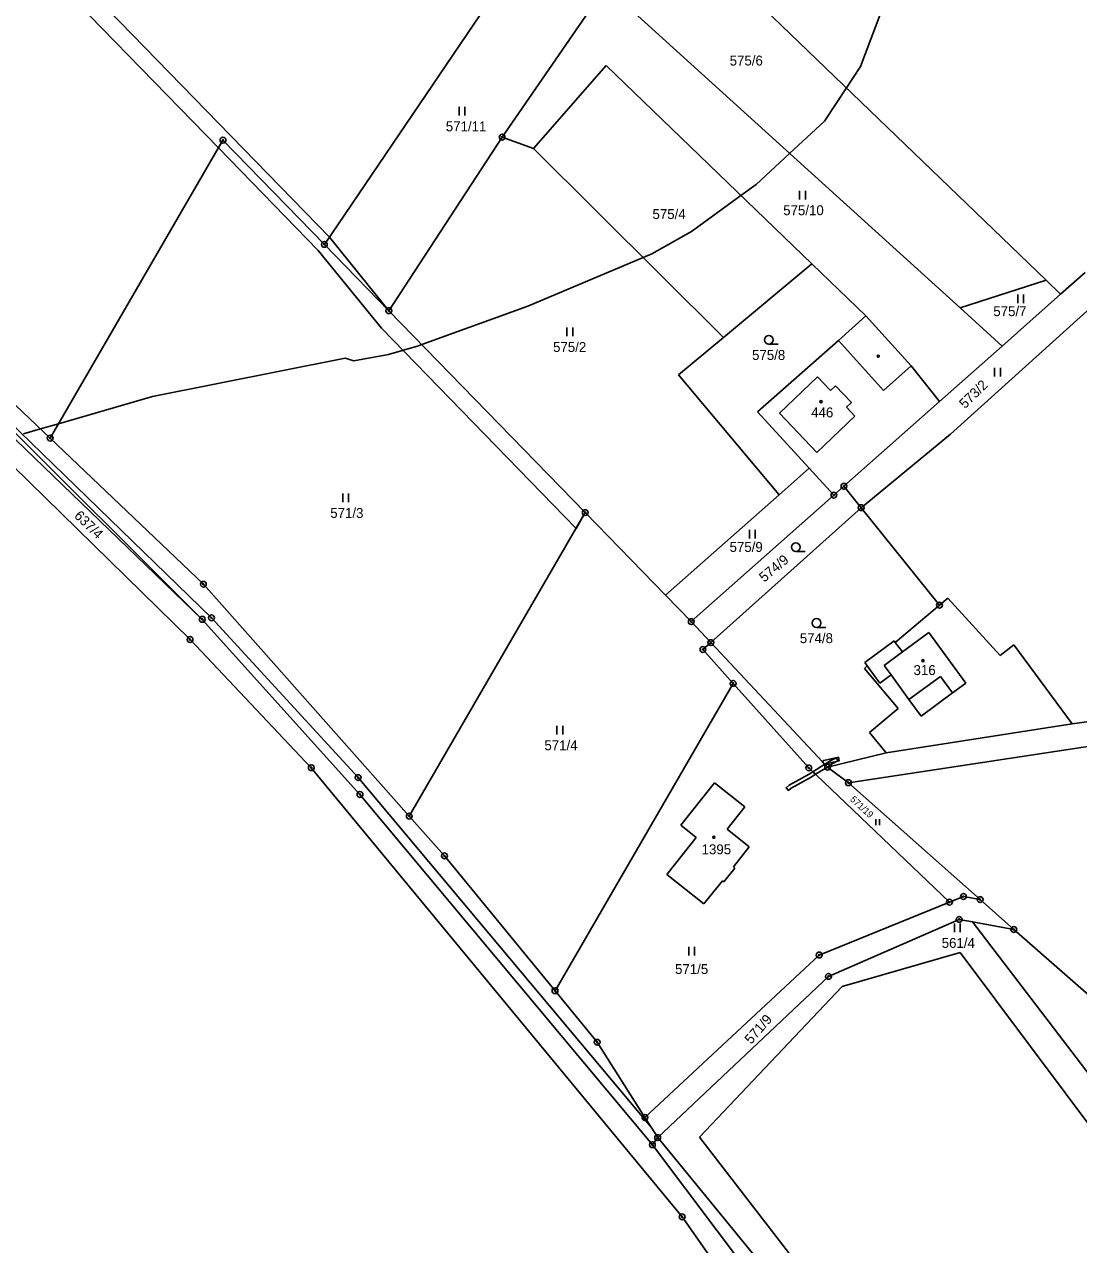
# Model space of a CAD drawing. Extents: x -439246 to -433691, y -1130252 to -1121148.
# Drawn here: x -437188.8 to -437008, y -1124679.8 to -1124470.4 of the extents above; entities that cross this region are included whole.
import ezdxf

# ---------------------------------------------------------------- set-up
doc = ezdxf.new("R2010")
doc.units = 0
for name, color, linetype in [('Vrstva 1', 7, 'Continuous'), ('Vrstva 18', 7, 'Continuous'), ('Vrstva 19', 7, 'Continuous'), ('Vrstva 24', 7, 'Continuous'), ('Vrstva 25', 7, 'Continuous'), ('Vrstva 3', 7, 'Continuous'), ('Vrstva 30', 7, 'Continuous'), ('Vrstva 37', 7, 'Continuous'), ('Vrstva 4', 7, 'Continuous'), ('Vrstva 52', 7, 'Continuous')]:
    doc.layers.add(name, color=color, linetype=linetype)

msp = doc.modelspace()

# ---------------------------------------------------------------- linework, layer by layer
at = {"layer": 'Vrstva 1'}
for p, q in [((-437160.38, -1124575.95), (-437208.36, -1124528.97)), ((-437194.11, -1124535.93), (-437156.69, -1124572.25)), ((-437156.69, -1124572.25), (-437131.53, -1124599.65)), ((-437139.58, -1124597.95), (-437160.38, -1124575.95)), ((-437044.66, -1124579.93), (-437039.61, -1124576.21)), ((-437039.61, -1124576.21), (-437039.43, -1124576.46)), ((-437044.72, -1124580.91), (-437044.24, -1124580.5)), ((-437044.24, -1124580.5), (-437044.66, -1124579.93)), ((-437075.97, -1124675.01), (-437139.58, -1124597.95)), ((-437131.53, -1124599.65), (-437081.31, -1124659.62)), ((-437076.2, -1124607.79), (-437070.42, -1124600.53)), ((-437070.42, -1124600.53), (-437065.2, -1124604.66)), ((-437065.2, -1124604.66), (-437068.26, -1124608.5)), ((-437073.55, -1124609.9), (-437076.2, -1124607.79)), ((-437068.26, -1124608.5), (-437064.45, -1124611.53)), ((-437078.59, -1124616.26), (-437073.55, -1124609.9)), ((-437064.45, -1124611.53), (-437067.17, -1124614.98)), ((-437066.93, -1124615.17), (-437068.84, -1124617.56)), ((-437067.17, -1124614.98), (-437066.93, -1124615.17)), ((-437072.23, -1124621.33), (-437078.59, -1124616.26)), ((-437069.08, -1124617.38), (-437072.23, -1124621.33)), ((-437068.84, -1124617.56), (-437069.08, -1124617.38)), ((-437082.35, -1124657.98), (-437081.31, -1124659.62)), ((-437081.31, -1124659.62), (-437080.17, -1124661.42)), ((-437062.23, -1124694.64), (-437075.97, -1124675.01))]:
    msp.add_line(p, q, dxfattribs=at)
for points in [[(-437099.75, -1124431.26), (-437013.54, -1124514.31)], [(-437098.98, -1124451.49), (-437137.34, -1124508.17)], [(-437106.86, -1124489.77), (-437089.09, -1124463.94)], [(-437028.31, -1124519.08), (-437089.09, -1124463.94)], [(-437101.46, -1124491.7), (-437089.02, -1124477.46)], [(-437089.02, -1124477.46), (-437053.74, -1124511.51)], [(-437154.73, -1124490.28), (-437184.38, -1124541.41)], [(-437137.34, -1124508.17), (-437154.73, -1124490.28)], [(-437126.28, -1124519.54), (-437106.86, -1124489.77)], [(-437106.86, -1124489.77), (-437101.46, -1124491.7)], [(-437068.88, -1124524.14), (-437101.46, -1124491.7)], [(-437229.3, -1124501.69), (-437158.28, -1124572.5)], [(-437230.24, -1124503.19), (-437158.28, -1124572.5)], [(-437137.34, -1124508.17), (-437126.28, -1124519.54)], [(-437184.38, -1124541.41), (-437218.63, -1124508.88)], [(-437053.74, -1124511.51), (-437068.88, -1124524.14)], [(-437053.74, -1124511.51), (-437044.48, -1124520.41)], [(-437028.31, -1124519.08), (-437013.54, -1124514.31)], [(-437013.54, -1124514.31), (-437011.05, -1124516.71)], [(-437011.05, -1124516.71), (-437006.87, -1124513)], [(-437029.94, -1124540.74), (-437002.46, -1124515.91)], [(-437021.1, -1124525.62), (-437011.05, -1124516.71)], [(-437126.28, -1124519.54), (-437092.59, -1124554.19)], [(-437044.48, -1124520.41), (-437049.17, -1124524.64)], [(-437044.48, -1124520.41), (-437036.71, -1124529)], [(-437021.1, -1124525.62), (-437028.31, -1124519.08)], [(-437068.88, -1124524.14), (-437076.58, -1124530.56)], [(-437049.17, -1124524.64), (-437063.05, -1124536.87)], [(-437031.84, -1124535.14), (-437021.1, -1124525.62)], [(-437036.71, -1124529), (-437031.84, -1124535.14)], [(-437076.58, -1124530.56), (-437059.35, -1124551.15)], [(-437048.22, -1124549.67), (-437031.84, -1124535.14)], [(-437063.05, -1124536.87), (-437054.16, -1124546.58)], [(-437184.38, -1124541.41), (-437158.09, -1124566.48)], [(-437045.28, -1124553.34), (-437029.94, -1124540.74)], [(-437059.35, -1124551.15), (-437054.16, -1124546.58)], [(-437054.16, -1124546.58), (-437049.94, -1124551.19)], [(-437049.94, -1124551.19), (-437048.22, -1124549.67)], [(-437045.28, -1124553.34), (-437048.22, -1124549.67)], [(-437078.84, -1124568.33), (-437059.35, -1124551.15)], [(-437074.41, -1124572.89), (-437049.94, -1124551.19)], [(-437092.59, -1124554.19), (-437122.78, -1124606.26)], [(-437078.84, -1124568.33), (-437092.59, -1124554.19)], [(-437071.04, -1124576.49), (-437045.28, -1124553.34)], [(-437031.83, -1124570.07), (-437045.28, -1124553.34)], [(-437158.09, -1124566.48), (-437122.78, -1124606.26)], [(-437074.41, -1124572.89), (-437078.84, -1124568.33)], [(-437031.83, -1124570.07), (-437030.41, -1124568.88)], [(-437030.41, -1124568.88), (-437021.45, -1124578.7)], [(-437031.83, -1124570.07), (-437039.43, -1124576.46)], [(-437158.28, -1124572.5), (-437131.23, -1124602.56)], [(-437071.04, -1124576.49), (-437074.41, -1124572.89)], [(-437072.41, -1124577.67), (-437071.04, -1124576.49)], [(-437051.02, -1124597.87), (-437071.04, -1124576.49)], [(-437019.1, -1124576.85), (-437021.45, -1124578.7)], [(-437019.1, -1124576.85), (-437009.08, -1124590.45)], [(-437067.21, -1124583.49), (-437072.41, -1124577.67)], [(-437044.72, -1124580.91), (-437038.94, -1124587.78)], [(-437097.78, -1124636.21), (-437067.21, -1124583.49)], [(-437054.26, -1124597.99), (-437067.21, -1124583.49)], [(-437009.08, -1124590.45), (-436975.07, -1124585.71)], [(-437038.94, -1124587.78), (-437043.86, -1124591.93)], [(-437047.46, -1124600.52), (-436975.87, -1124589.68)], [(-437043.86, -1124591.93), (-437040.96, -1124595.38)], [(-437040.96, -1124595.38), (-437009.08, -1124590.45)], [(-437051.02, -1124597.87), (-437040.96, -1124595.38)], [(-437030.11, -1124621.02), (-437054.26, -1124597.99)], [(-437047.46, -1124600.52), (-437051.02, -1124597.87)], [(-437024.86, -1124620.58), (-437047.46, -1124600.52)], [(-437131.23, -1124602.56), (-437081.08, -1124662.64)], [(-437122.78, -1124606.26), (-437116.73, -1124613.07)], [(-437116.73, -1124613.07), (-437097.78, -1124636.21)], [(-437052.48, -1124630.09), (-437030.11, -1124621.02)], [(-437030.11, -1124621.02), (-437027.73, -1124620.05)], [(-437027.73, -1124620.05), (-437024.86, -1124620.58)], [(-437024.86, -1124620.58), (-437019.08, -1124625.71)], [(-437028.46, -1124623.98), (-437050.88, -1124633.76)], [(-437026.18, -1124624.4), (-437028.46, -1124623.98)], [(-436988.93, -1124673.14), (-437026.18, -1124624.4)], [(-437019.08, -1124625.71), (-437026.18, -1124624.4)], [(-437019.08, -1124625.71), (-436938.54, -1124696.3)], [(-437048.54, -1124635.49), (-437028.26, -1124629.67)], [(-437028.26, -1124629.67), (-436992.11, -1124678.02)], [(-437082.35, -1124657.98), (-437052.48, -1124630.09)], [(-437080.17, -1124661.42), (-437050.88, -1124633.76)], [(-437073, -1124661.34), (-437048.54, -1124635.49)], [(-437097.78, -1124636.21), (-437090.54, -1124645.06)], [(-437090.54, -1124645.06), (-437082.35, -1124657.98)], [(-437080.17, -1124661.42), (-437081.08, -1124662.64)], [(-437081.08, -1124662.64), (-437058.87, -1124692.18)], [(-437080.17, -1124661.42), (-437053.17, -1124694.4)], [(-437011.99, -1124740.43), (-437073, -1124661.34)]]:
    msp.add_lwpolyline(points, dxfattribs=at)
at = {"layer": 'Vrstva 24'}
for centre, radius in [((-437106.86, -1124489.77), 0.5), ((-437154.73, -1124490.28), 0.5), ((-437154.73, -1124490.28), 0.1), ((-437106.86, -1124489.77), 0.1), ((-437137.34, -1124508.17), 0.5), ((-437137.34, -1124508.17), 0.1), ((-437126.28, -1124519.54), 0.5), ((-437126.28, -1124519.54), 0.1), ((-437184.38, -1124541.41), 0.5), ((-437184.38, -1124541.41), 0.1), ((-437048.22, -1124549.67), 0.5), ((-437048.22, -1124549.67), 0.1), ((-437049.94, -1124551.19), 0.5), ((-437049.94, -1124551.19), 0.1), ((-437092.59, -1124554.19), 0.5), ((-437092.59, -1124554.19), 0.1), ((-437045.28, -1124553.34), 0.5), ((-437045.28, -1124553.34), 0.1), ((-437158.09, -1124566.48), 0.5), ((-437158.09, -1124566.48), 0.1), ((-437031.83, -1124570.07), 0.5), ((-437031.83, -1124570.07), 0.1), ((-437158.28, -1124572.5), 0.5), ((-437158.28, -1124572.5), 0.1), ((-437156.69, -1124572.25), 0.5), ((-437156.69, -1124572.25), 0.1), ((-437074.41, -1124572.89), 0.5), ((-437074.41, -1124572.89), 0.1), ((-437160.38, -1124575.95), 0.5), ((-437160.38, -1124575.95), 0.1), ((-437072.41, -1124577.67), 0.5), ((-437071.04, -1124576.49), 0.5), ((-437071.04, -1124576.49), 0.1), ((-437072.41, -1124577.67), 0.1), ((-437067.21, -1124583.49), 0.5), ((-437067.21, -1124583.49), 0.1), ((-437139.58, -1124597.95), 0.5), ((-437139.58, -1124597.95), 0.1), ((-437054.26, -1124597.99), 0.5), ((-437054.26, -1124597.99), 0.1), ((-437051.02, -1124597.87), 0.5), ((-437051.02, -1124597.87), 0.1), ((-437131.53, -1124599.65), 0.5), ((-437131.53, -1124599.65), 0.1), ((-437047.46, -1124600.52), 0.5), ((-437047.46, -1124600.52), 0.1), ((-437131.23, -1124602.56), 0.5), ((-437131.23, -1124602.56), 0.1), ((-437122.78, -1124606.26), 0.5), ((-437122.78, -1124606.26), 0.1), ((-437116.73, -1124613.07), 0.5), ((-437116.73, -1124613.07), 0.1), ((-437030.11, -1124621.02), 0.5), ((-437030.11, -1124621.02), 0.1), ((-437027.73, -1124620.05), 0.5), ((-437027.73, -1124620.05), 0.1), ((-437024.86, -1124620.58), 0.5), ((-437024.86, -1124620.58), 0.1), ((-437028.46, -1124623.98), 0.5), ((-437028.46, -1124623.98), 0.1), ((-437019.08, -1124625.71), 0.5), ((-437019.08, -1124625.71), 0.1), ((-437052.48, -1124630.09), 0.5), ((-437052.48, -1124630.09), 0.1), ((-437050.88, -1124633.76), 0.5), ((-437050.88, -1124633.76), 0.1), ((-437097.78, -1124636.21), 0.5), ((-437097.78, -1124636.21), 0.1), ((-437090.54, -1124645.06), 0.5), ((-437090.54, -1124645.06), 0.1), ((-437082.35, -1124657.98), 0.5), ((-437082.35, -1124657.98), 0.1), ((-437080.17, -1124661.42), 0.5), ((-437081.08, -1124662.64), 0.5), ((-437081.08, -1124662.64), 0.1), ((-437080.17, -1124661.42), 0.1), ((-437075.97, -1124675.01), 0.5), ((-437075.97, -1124675.01), 0.1)]:
    msp.add_circle(centre, radius, dxfattribs=at)
at = {"layer": 'Vrstva 25'}
for p, q in [((-437114.24, -1124486.07), (-437114.24, -1124484.57)), ((-437113.24, -1124486.07), (-437113.24, -1124484.57)), ((-437055.84, -1124500.46), (-437055.84, -1124498.96)), ((-437054.84, -1124500.46), (-437054.84, -1124498.96)), ((-437018.41, -1124518.27), (-437018.41, -1124516.77)), ((-437017.41, -1124518.27), (-437017.41, -1124516.77)), ((-437095.74, -1124523.93), (-437095.74, -1124522.43)), ((-437094.74, -1124523.93), (-437094.74, -1124522.43)), ((-437061.11, -1124525.29), (-437059.51, -1124525.29)), ((-437022.39, -1124530.84), (-437022.39, -1124529.34)), ((-437021.39, -1124530.84), (-437021.39, -1124529.34)), ((-437134.19, -1124552.4), (-437134.19, -1124550.9)), ((-437133.19, -1124552.4), (-437133.19, -1124550.9)), ((-437064.43, -1124558.65), (-437064.43, -1124557.15)), ((-437063.43, -1124558.65), (-437063.43, -1124557.15)), ((-437056.48, -1124560.86), (-437054.88, -1124560.86)), ((-437052.91, -1124573.88), (-437051.31, -1124573.88)), ((-437097.45, -1124592.26), (-437097.45, -1124590.76)), ((-437096.45, -1124592.26), (-437096.45, -1124590.76)), ((-437042.78, -1124607.82), (-437042.78, -1124606.81)), ((-437042.1, -1124607.82), (-437042.1, -1124606.81)), ((-437029.27, -1124626.17), (-437029.27, -1124624.67)), ((-437028.27, -1124626.17), (-437028.27, -1124624.67)), ((-437074.85, -1124630.2), (-437074.85, -1124628.7)), ((-437073.85, -1124630.2), (-437073.85, -1124628.7))]:
    msp.add_line(p, q, dxfattribs=at)
for centre, radius in [((-437061.11, -1124524.54), 0.75), ((-437042.33, -1124527.34), 0.175), ((-437052.16, -1124535.15), 0.175), ((-437056.48, -1124560.11), 0.75), ((-437052.91, -1124573.13), 0.75), ((-437034.67, -1124579.59), 0.175), ((-437070.53, -1124609.89), 0.175)]:
    msp.add_circle(centre, radius, dxfattribs=at)
at = {"layer": 'Vrstva 3'}
for points in [[(-437059.27, -1124537.13), (-437052.76, -1124530.92)], [(-437052.76, -1124530.92), (-437050.54, -1124533.25)], [(-437050.54, -1124533.25), (-437049.65, -1124532.41)], [(-437049.65, -1124532.41), (-437046.91, -1124535.27)], [(-437046.91, -1124535.27), (-437047.8, -1124536.12)], [(-437052.85, -1124543.86), (-437059.27, -1124537.13)], [(-437052.85, -1124543.86), (-437046.34, -1124537.65)], [(-437047.8, -1124536.12), (-437046.34, -1124537.65)], [(-437038.2, -1124578.08), (-437033.67, -1124574.76)], [(-437033.67, -1124574.76), (-437027.3, -1124583.45)], [(-437038.2, -1124578.08), (-437041.35, -1124580.39)], [(-437041.35, -1124580.39), (-437040.15, -1124582.04)], [(-437037.07, -1124586.26), (-437040.15, -1124582.04)], [(-437031.66, -1124582.29), (-437037.07, -1124586.26)], [(-437029.58, -1124585.12), (-437031.66, -1124582.29)], [(-437027.3, -1124583.45), (-437029.58, -1124585.12)], [(-437076.2, -1124607.79), (-437070.42, -1124600.53)], [(-437070.42, -1124600.53), (-437065.2, -1124604.66)], [(-437065.2, -1124604.66), (-437068.26, -1124608.5)], [(-437073.55, -1124609.9), (-437076.2, -1124607.79)], [(-437068.26, -1124608.5), (-437064.45, -1124611.53)], [(-437078.59, -1124616.26), (-437073.55, -1124609.9)], [(-437064.45, -1124611.53), (-437067.17, -1124614.98)], [(-437066.93, -1124615.17), (-437068.84, -1124617.56)], [(-437067.17, -1124614.98), (-437066.93, -1124615.17)], [(-437072.23, -1124621.33), (-437078.59, -1124616.26)], [(-437069.08, -1124617.38), (-437072.23, -1124621.33)], [(-437068.84, -1124617.56), (-437069.08, -1124617.38)]]:
    msp.add_lwpolyline(points, dxfattribs=at)
at = {"layer": 'Vrstva 30'}
for points in [[(-437188.73, -1124457.46), (-437187.91, -1124456.04), (-437187.19, -1124454.8), (-437136.48, -1124506.91), (-437137.34, -1124508.17)], [(-437155.52, -1124491.63), (-437188.73, -1124457.46)], [(-437094.15, -1124556.89), (-437127.56, -1124522.53), (-437138.42, -1124509.21), (-437155.52, -1124491.63), (-437154.73, -1124490.28), (-437137.34, -1124508.17), (-437126.28, -1124519.54), (-437092.59, -1124554.19), (-437094.15, -1124556.89)], [(-437137.34, -1124508.17), (-437154.73, -1124490.28), (-437155.52, -1124491.63)], [(-437136.48, -1124506.91), (-437126.28, -1124519.54), (-437137.34, -1124508.17), (-437136.48, -1124506.91)], [(-437051.02, -1124597.87), (-437053.11, -1124599.09), (-437053.56, -1124598.66), (-437051.5, -1124597.36), (-437050.45, -1124596.69), (-437049.51, -1124596.25), (-437049.26, -1124596.8), (-437050.16, -1124597.22), (-437051.02, -1124597.87)], [(-437049.16, -1124596.17), (-437049.03, -1124596.76), (-437051.53, -1124597.32), (-437051.95, -1124596.88), (-437051.69, -1124596.74), (-437049.16, -1124596.17)], [(-437053.11, -1124599.09), (-437053.86, -1124599.56), (-437057.3, -1124601.45), (-437057.74, -1124601.85), (-437058.14, -1124601.4), (-437057.64, -1124600.95), (-437054.16, -1124599.04), (-437053.56, -1124598.66), (-437053.11, -1124599.09)]]:
    msp.add_lwpolyline(points, dxfattribs=at)
at = {"layer": 'Vrstva 37'}
for centre in [(-437052.16, -1124535.15), (-437034.67, -1124579.59), (-437070.53, -1124609.89)]:
    msp.add_circle(centre, 0.175, dxfattribs=at)
at = {"layer": 'Vrstva 4'}
for p, q in [((-437038.2, -1124578.08), (-437033.67, -1124574.76)), ((-437033.67, -1124574.76), (-437027.3, -1124583.45)), ((-437039.43, -1124576.46), (-437038.2, -1124578.08)), ((-437038.2, -1124578.08), (-437041.35, -1124580.39)), ((-437042.08, -1124583.43), (-437044.24, -1124580.5)), ((-437041.35, -1124580.39), (-437040.15, -1124582.04)), ((-437040.15, -1124582.04), (-437042.08, -1124583.43)), ((-437037.07, -1124586.26), (-437040.15, -1124582.04)), ((-437031.66, -1124582.29), (-437037.07, -1124586.26)), ((-437029.58, -1124585.12), (-437031.66, -1124582.29)), ((-437027.3, -1124583.45), (-437029.58, -1124585.12)), ((-437035, -1124589.1), (-437029.58, -1124585.12)), ((-437037.07, -1124586.26), (-437035, -1124589.1))]:
    msp.add_line(p, q, dxfattribs=at)
for points in [[(-437041.41, -1124533.24), (-437049.17, -1124524.64)], [(-437036.71, -1124529), (-437041.41, -1124533.24)], [(-437059.27, -1124537.13), (-437052.76, -1124530.92)], [(-437052.76, -1124530.92), (-437050.54, -1124533.25)], [(-437050.54, -1124533.25), (-437049.65, -1124532.41)], [(-437049.65, -1124532.41), (-437046.91, -1124535.27)], [(-437046.91, -1124535.27), (-437047.8, -1124536.12)], [(-437052.85, -1124543.86), (-437059.27, -1124537.13)], [(-437052.85, -1124543.86), (-437046.34, -1124537.65)], [(-437047.8, -1124536.12), (-437046.34, -1124537.65)]]:
    msp.add_lwpolyline(points, dxfattribs=at)
at = {"layer": 'Vrstva 52'}
msp.add_lwpolyline([(-437040.26, -1124464), (-437045.38, -1124477.63), (-437047.8, -1124481.3), (-437051.56, -1124487), (-437057.55, -1124492.56), (-437063.27, -1124497.87), (-437065.89, -1124499.78), (-437074.35, -1124505.96), (-437081.17, -1124509.8), (-437082.66, -1124510.42), (-437102.47, -1124518.74), (-437120.63, -1124525.35), (-437121.21, -1124525.56), (-437126.33, -1124527.05), (-437132.29, -1124528.12), (-437133.78, -1124527.69), (-437166.8, -1124534.29), (-437182.95, -1124538.95), (-437186.03, -1124539.84), (-437188.96, -1124540.69)], dxfattribs=at)

# ---------------------------------------------------------------- texts
at = {"layer": 'Vrstva 18'}
for s, p in [('575/6', (-437067.82, -1124477.48)), ('571/11', (-437116.51, -1124488.77)), ('575/4', (-437081.06, -1124503.82)), ('575/10', (-437058.64, -1124503.16)), ('575/7', (-437022.6, -1124520.48)), ('575/2', (-437098.11, -1124526.63)), ('575/8', (-437063.98, -1124527.99)), ('571/3', (-437136.33, -1124555.1)), ('575/9', (-437067.84, -1124560.93)), ('574/8', (-437055.79, -1124576.58)), ('571/4', (-437099.6, -1124594.96)), ('561/4', (-437031.45, -1124628.87)), ('571/5', (-437077.19, -1124633.35))]:
    msp.add_text(s, height=1.7, dxfattribs=at).set_placement(p)
for s, height, rotation, p in [('573/2', 1.7, 44.5614, (-437027.46, -1124536.45)), ('637/4', 1.7, 315.6034, (-437180.37, -1124554.87)), ('574/9', 1.7, 39.8736, (-437061.89, -1124566.21)), ('571/19', 1.14, 317.242, (-437047.25, -1124603.51)), ('571/9', 1.7, 48.8434, (-437064.15, -1124645.5))]:
    msp.add_text(s, height=height, rotation=rotation, dxfattribs=at).set_placement(p)
at = {"layer": 'Vrstva 19'}
for s, p in [('446', (-437053.84, -1124537.85)), ('316', (-437036.28, -1124582.06)), ('1395', (-437072.63, -1124612.81))]:
    msp.add_text(s, height=1.7, dxfattribs=at).set_placement(p)

doc.saveas('drawing.dxf')
